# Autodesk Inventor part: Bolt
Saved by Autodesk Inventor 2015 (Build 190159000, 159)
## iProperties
Created: 2015-04
Part Number: Bolt
Material: Generic
Document SubType Name: Modeling
Designer: Gabriel Cabellos
Density: 1 g/cm^3
Appearance: Default
Author: Gabriel Cabellos
Sending System: SolidWorks 2011
Last Author: Pets
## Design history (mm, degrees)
node "Bolt.ipt1"
node "Chamfer1"
node "Base1"
